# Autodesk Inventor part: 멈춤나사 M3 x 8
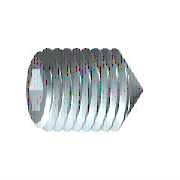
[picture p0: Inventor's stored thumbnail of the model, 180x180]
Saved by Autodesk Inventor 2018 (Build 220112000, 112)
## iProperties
IsCustomPart: 1
Created: 2012-02
Part Number: 멈춤나사 M3 x 8
Material: 강철, 연강
Description: 6각 소켓 머리 없는 멈춤 나사
Document SubType Name: Modeling
Standard: KS B 1028
Designer: test
Standards Organization: KS
Language: ko-KR
Size Designation: 원추점 M3x8
Categories: <MemberInstance><Categories><Category DisplayName="조임쇠" InternalName="e4da775c-781d-43d5-af7c-5136215cf5a6" Mnemonic="FSTN"><Category DisplayName="볼트" InternalN
Density: 1 g/cm^3
Appearance: 강철
Author: test
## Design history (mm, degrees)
sketch "스케치1"
  geometry: L1 (0, 0)-(5.5, 0); L2 (8, 0.866)-(8, 1.5); L3 (8, 1.5)-(0, 1.5); L4 (8, 0.866)-(6, 0.866); L5 (6, 0.866)-(5.5, 0); L6 (0, -0.3)-(0, 1.8) reference; L7 (0, 1.5)-(0, 0)
  constraints: 13 end point, 3 parallel, 1 collinear, 1 perpendicular, 1 point on line
  dimensions: "d0" = 2 distance of L2.start L4.end (= INTI); "d1" = 60 deg angle of L5 L1; "d2" = 3 diameter of L3 L1 (= NND); "d3" = 1.73205 diameter of L4 L1 (= 1.1547 x SW); "d5" = 8 distance from line of L2 L3.end (= NLG)
revolve "본체" sketch "스케치1" stored, may be unused: angle "d6" = 90 deg
sketch "스케치2"
  geometry: L1 (-0.433, 0.75)-(0.433, 0.75); L2 (0.433, 0.75)-(0.866, 0); L3 (0.866, 0)-(0.433, -0.75); L4 (0.433, -0.75)-(-0.433, -0.75); L5 (-0.433, -0.75)-(-0.866, 0); L6 (-0.866, 0)-(-0.433, 0.75); 3 further points
  constraints: 12 end point, 1 coincident, 1 horizontal, 13 other
extrude "슬롯" join sketch "스케치2" taper "d7" = 0 deg; stored distance "d21" = 10
workaxis "Work Axis1"
workplane "Work Plane1"
sketch "스케치4"
  geometry: L1 (0, 0.15)-(-1.35, 1.5) reference; L2 (0, -0.15)-(-1.35, -1.5) reference; L3 (-1.35, -1.5)-(0.15, 0); L4 (-1.35, 1.5)-(0.15, 0); 2 further points
  constraints: 4 end point, 1 coincident, 1 collinear, 1 horizontal alignment
body "Solid1"
feature "스레드" dims "d12" = 8 (= NLG), "d13" = 0
chamfer "모따기1" distance "d8" = 1.35 (computed from NND, SPD, FAWI); stored, may be unused: angle "d9" = 45 deg (= FAWI), second distance "d34" = 1.35 (computed from NND, SPD, FAWI)
chamfer "모따기2" distance "d10" = 0.30673 (= -0.5 x GD1 + 0.5 x NND); stored, may be unused: angle "d11" = 45 deg (= FAWI), second distance "d35" = 0.30673 (= -0.5 x GD1 + 0.5 x NND)
other parameters: "NND" = 3 [user parameter; used in 5 equation terms], "NLG" = 8 [user parameter; used in 2 equation terms], "INTI" = 2 [user parameter; used in 1 equation term], "FAWI" = 45 deg [user parameter; used in 4 equation terms], "SW" = 1.5 [user parameter; used in 2 equation terms], "GD1" = 2.38655 (= THREADDIA - 1.2269 x PTC) [user parameter; used in 2 equation terms], "d4" = 0, "FAWI1" = 45 deg [user parameter], "SPD" = 0.3 [user parameter; used in 2 equation terms], "d36" = 0, "d37" = 0, "GUL" = 0.30673 (= 0.61345 x PTC) [user parameter], "TOA" = 30 deg [user parameter], "THREADDIA" = 3 [user parameter; used in 1 equation term], "PTC" = 0.5 [user parameter; used in 4 equation terms], "GAL" = 0.30673 (= 0.61345 x PTC) [user parameter], "E0" = 1.7325 (= 1.155 x SW) [user parameter]
